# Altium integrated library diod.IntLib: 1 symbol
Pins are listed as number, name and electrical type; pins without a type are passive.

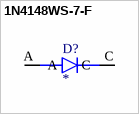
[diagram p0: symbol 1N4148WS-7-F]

## 1N4148WS-7-F
designator D?
Diode Standard 75 V 150mA Surface Mount SOD-323; MP: 1N4148WS-7-F; MF: Diodes Inc.
footprint SOD2513X120N
footprint SOD2513X120N
pins: A, C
